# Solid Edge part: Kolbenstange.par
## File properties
Username: bmolnar
Dokumentum tartalom típus: 0
Author: bmolnar
Last saved by: bmolnar
Revision: 92
Sűrűség: 0,000 kg/m^3
Pontosság: 0,990
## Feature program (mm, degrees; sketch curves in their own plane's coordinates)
base feature "unnamed BaseFeature 1"
sketch for "Furat_1" plane through (-155, 0, 0) normal (-1, 0, 0) x-axis (0, 1, 0)
  hole centre (0, 0) bore radius 2.4585
hole "Furat_1" nominal diameter 6 finite  ThreadDepth = 15 mm; StartChamferOffset = 0.7 mm; StartChamferAngle = 45 deg; VBottomAngle = 118 deg
sketch for "Kihúzás_1" plane through (23.5, 0, 0) normal (1, 0, 0) x-axis (0, -1, 0)
  circle centre (0, 0) radius 12.5
extrude "Kihúzás_1" add finite 14 along +normal
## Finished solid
Body 1: solid body, 14 faces, 20 edges, 8 vertices.
  Faces by surface: plane 7, cylinder 4, cone 2, torus 1
  Edges by curve: circle 10, line 6, ellipse 2, intersection 2
Bounding box of the edges (mm; curved faces can reach further): 192.500 x 25.000 x 25.000, from (-155, -12.5, -12.5) to (37.5, 12.5, 12.5).
Cylindrical faces by radius (mm): R2.4585 x2, R5 x1, R12.5 x1
Conical faces (half-angle, radius in mm at the cone's reference point): 45 deg R3.1585 x1, 59 deg R2.4585 x1
Toroidal faces (ring radius, tube radius in mm): R3.8 r1.2 x1
Planar faces by outward normal: +x 1, +z 1, -x 2, -z 1, oblique 2
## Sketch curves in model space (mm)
circle centre (23.5, 0, 0) radius 12.5
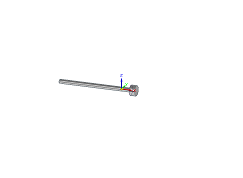
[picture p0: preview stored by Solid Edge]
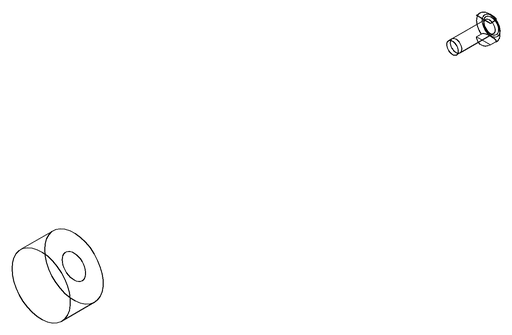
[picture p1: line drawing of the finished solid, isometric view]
